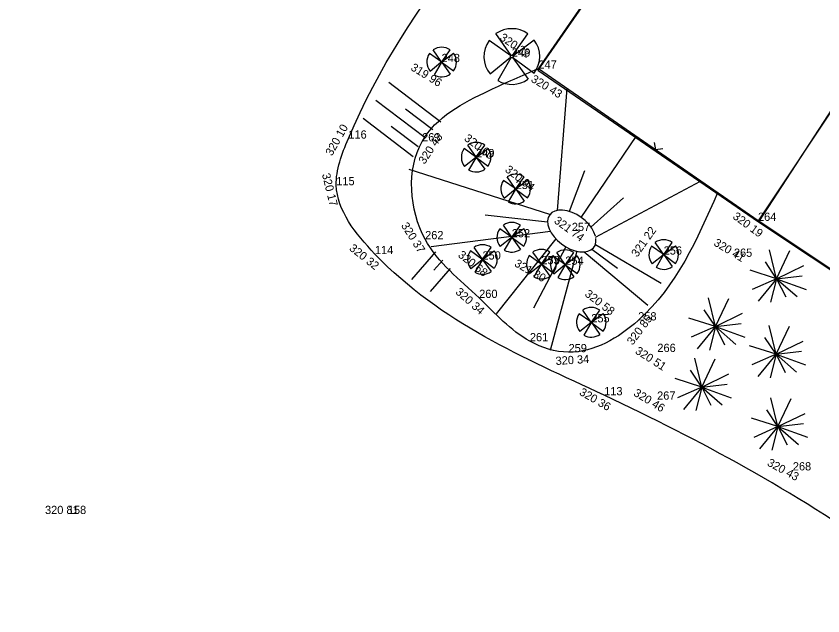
# Model space of a CAD drawing. Extents: x -742884 to -742543, y -1054677 to -1054433.
# Drawn here: x -742706.11 to -742676.68, y -1054570.07 to -1054548.2 of the extents above; entities that cross this region are included whole.
import ezdxf

# ---------------------------------------------------------------- set-up
doc = ezdxf.new("R2010")
doc.units = 0
for name, color, linetype in [('Vrstva 1', 7, 'Continuous'), ('Vrstva 10', 7, 'Continuous'), ('Vrstva 11', 7, 'Continuous'), ('Vrstva 2', 7, 'Continuous'), ('Vrstva 3', 7, 'Continuous'), ('Vrstva 5', 7, 'Continuous'), ('Vrstva 50', 7, 'Continuous'), ('Vrstva 6', 7, 'Continuous')]:
    doc.layers.add(name, color=color, linetype=linetype)

# ---------------------------------------------------------------- blocks, each defined once
blk = doc.blocks.new('Z15')
at = {"layer": 'Vrstva 2'}
for p, q in [((-10, 2), (-8, 6)), ((-10, -2), (-10, 2)), ((-8, 6), (-6, 8)), ((-6, 8), (-2, 10)), ((-2, 10), (2, 10)), ((2, 10), (6, 8)), ((6, 8), (8, 6)), ((8, 6), (10, 2)), ((10, 2), (10, -2)), ((-8, -6), (-10, -2)), ((-6, -8), (-8, -6)), ((-2, -10), (-6, -8)), ((2, -10), (-2, -10)), ((6, -8), (2, -10)), ((8, -6), (6, -8)), ((10, -2), (8, -6))]:
    blk.add_line(p, q, dxfattribs=at)

msp = doc.modelspace()

# ---------------------------------------------------------------- linework, layer by layer
at = {"layer": 'Vrstva 1'}
for p, q in [((-742690.59, -1054549.88), (-742690.59, -1054549.88)), ((-742688.03, -1054549.68), (-742688.03, -1054549.68)), ((-742687.06, -1054550.12), (-742687.06, -1054550.12)), ((-742693.99, -1054552.67), (-742693.99, -1054552.67)), ((-742691.3, -1054552.77), (-742691.3, -1054552.77)), ((-742689.33, -1054553.35), (-742689.33, -1054553.35)), ((-742694.43, -1054554.37), (-742694.43, -1054554.37)), ((-742687.89, -1054554.51), (-742687.89, -1054554.51)), ((-742679.05, -1054555.67), (-742679.05, -1054555.67)), ((-742685.84, -1054556.04), (-742685.84, -1054556.04)), ((-742691.19, -1054556.34), (-742691.19, -1054556.34)), ((-742688.03, -1054556.27), (-742688.03, -1054556.27)), ((-742693.02, -1054556.88), (-742693.02, -1054556.88)), ((-742682.49, -1054556.9), (-742682.49, -1054556.9)), ((-742679.93, -1054556.98), (-742679.93, -1054556.98)), ((-742689.1, -1054557.08), (-742689.1, -1054557.08)), ((-742686.95, -1054557.25), (-742686.95, -1054557.25)), ((-742686.08, -1054557.27), (-742686.08, -1054557.27)), ((-742689.22, -1054558.48), (-742689.22, -1054558.48)), ((-742685.13, -1054559.37), (-742685.13, -1054559.37)), ((-742683.42, -1054559.3), (-742683.42, -1054559.3)), ((-742687.37, -1054560.06), (-742687.37, -1054560.06)), ((-742685.96, -1054560.46), (-742685.96, -1054560.46)), ((-742682.72, -1054560.45), (-742682.72, -1054560.45)), ((-742684.66, -1054562.03), (-742684.66, -1054562.03)), ((-742682.73, -1054562.19), (-742682.73, -1054562.19)), ((-742677.78, -1054564.77), (-742677.78, -1054564.77)), ((-742704.22, -1054566.36), (-742704.22, -1054566.36))]:
    msp.add_line(p, q, dxfattribs=at)
at = {"layer": 'Vrstva 10'}
for p, q in [((-742688.054, -1054549.64), (-742688.608, -1054548.843)), ((-742688, -1054549.64), (-742687.439, -1054548.849)), ((-742687.992, -1054549.651), (-742687.212, -1054549.074)), ((-742688.07, -1054549.646), (-742688.858, -1054549.09)), ((-742690.611, -1054549.861), (-742691.031, -1054549.566)), ((-742690.602, -1054549.858), (-742690.897, -1054549.435)), ((-742690.574, -1054549.858), (-742690.276, -1054549.438)), ((-742690.57, -1054549.864), (-742690.156, -1054549.558)), ((-742690.611, -1054549.898), (-742691.01, -1054550.218)), ((-742690.605, -1054549.904), (-742690.862, -1054550.345)), ((-742690.573, -1054549.901), (-742690.276, -1054550.319)), ((-742690.566, -1054549.896), (-742690.156, -1054550.199)), ((-742688.071, -1054549.715), (-742688.82, -1054550.317)), ((-742688.06, -1054549.725), (-742688.541, -1054550.556)), ((-742687.996, -1054549.72), (-742687.438, -1054550.507)), ((-742687.986, -1054549.709), (-742687.212, -1054550.282)), ((-742689.342, -1054553.328), (-742689.637, -1054552.905)), ((-742689.314, -1054553.328), (-742689.016, -1054552.908)), ((-742689.351, -1054553.331), (-742689.771, -1054553.036)), ((-742689.31, -1054553.334), (-742688.896, -1054553.028)), ((-742689.351, -1054553.368), (-742689.75, -1054553.688)), ((-742689.345, -1054553.374), (-742689.602, -1054553.815)), ((-742689.313, -1054553.371), (-742689.016, -1054553.789)), ((-742689.306, -1054553.366), (-742688.896, -1054553.669)), ((-742687.902, -1054554.488), (-742688.197, -1054554.065)), ((-742687.874, -1054554.488), (-742687.576, -1054554.068)), ((-742687.911, -1054554.491), (-742688.331, -1054554.196)), ((-742687.87, -1054554.494), (-742687.456, -1054554.188)), ((-742687.911, -1054554.528), (-742688.31, -1054554.848)), ((-742687.905, -1054554.534), (-742688.162, -1054554.975)), ((-742687.873, -1054554.531), (-742687.576, -1054554.949)), ((-742687.866, -1054554.526), (-742687.456, -1054554.829)), ((-742688.042, -1054556.248), (-742688.337, -1054555.825)), ((-742688.014, -1054556.248), (-742687.716, -1054555.828)), ((-742688.051, -1054556.251), (-742688.471, -1054555.956)), ((-742688.01, -1054556.254), (-742687.596, -1054555.948)), ((-742688.051, -1054556.288), (-742688.45, -1054556.608)), ((-742688.045, -1054556.294), (-742688.302, -1054556.735)), ((-742688.013, -1054556.291), (-742687.716, -1054556.709)), ((-742688.006, -1054556.286), (-742687.596, -1054556.589)), ((-742689.112, -1054557.058), (-742689.407, -1054556.635)), ((-742689.084, -1054557.058), (-742688.786, -1054556.638)), ((-742682.511, -1054556.881), (-742682.931, -1054556.586)), ((-742682.502, -1054556.878), (-742682.797, -1054556.455)), ((-742682.474, -1054556.878), (-742682.176, -1054556.458)), ((-742682.47, -1054556.884), (-742682.056, -1054556.578)), ((-742678.372, -1054557.78), (-742678.629, -1054556.73)), ((-742689.121, -1054557.061), (-742689.541, -1054556.766)), ((-742689.08, -1054557.064), (-742688.666, -1054556.758)), ((-742686.971, -1054557.231), (-742687.391, -1054556.936)), ((-742686.962, -1054557.228), (-742687.257, -1054556.805)), ((-742686.934, -1054557.228), (-742686.636, -1054556.808)), ((-742686.93, -1054557.234), (-742686.516, -1054556.928)), ((-742686.101, -1054557.251), (-742686.521, -1054556.956)), ((-742686.092, -1054557.248), (-742686.387, -1054556.825)), ((-742686.064, -1054557.248), (-742685.766, -1054556.828)), ((-742686.06, -1054557.254), (-742685.646, -1054556.948)), ((-742682.511, -1054556.918), (-742682.91, -1054557.238)), ((-742682.505, -1054556.924), (-742682.762, -1054557.365)), ((-742682.473, -1054556.921), (-742682.176, -1054557.339)), ((-742682.466, -1054556.916), (-742682.056, -1054557.219)), ((-742678.372, -1054557.78), (-742677.887, -1054556.755)), ((-742689.121, -1054557.098), (-742689.52, -1054557.418)), ((-742689.115, -1054557.104), (-742689.372, -1054557.545)), ((-742689.083, -1054557.101), (-742688.786, -1054557.519)), ((-742689.076, -1054557.096), (-742688.666, -1054557.399)), ((-742686.971, -1054557.268), (-742687.37, -1054557.588)), ((-742686.965, -1054557.274), (-742687.222, -1054557.715)), ((-742686.933, -1054557.271), (-742686.636, -1054557.689)), ((-742686.926, -1054557.266), (-742686.516, -1054557.569)), ((-742686.101, -1054557.288), (-742686.5, -1054557.608)), ((-742686.095, -1054557.294), (-742686.352, -1054557.735)), ((-742686.063, -1054557.291), (-742685.766, -1054557.709)), ((-742686.056, -1054557.286), (-742685.646, -1054557.589)), ((-742678.372, -1054557.78), (-742678.782, -1054557.169)), ((-742678.372, -1054557.78), (-742677.38, -1054557.301)), ((-742678.372, -1054557.78), (-742679.341, -1054557.473)), ((-742678.372, -1054557.78), (-742679.257, -1054558.173)), ((-742678.372, -1054557.78), (-742679.042, -1054558.594)), ((-742678.372, -1054557.78), (-742678.592, -1054558.639)), ((-742678.376, -1054557.774), (-742678.376, -1054557.774)), ((-742678.372, -1054557.78), (-742677.44, -1054557.674)), ((-742678.372, -1054557.78), (-742678.372, -1054557.78)), ((-742678.372, -1054557.78), (-742678.036, -1054558.444)), ((-742678.372, -1054557.78), (-742677.297, -1054558.169)), ((-742678.372, -1054557.78), (-742677.626, -1054558.433)), ((-742678.372, -1054557.78), (-742678.372, -1054557.78)), ((-742680.602, -1054559.52), (-742680.859, -1054558.47)), ((-742680.602, -1054559.52), (-742680.117, -1054558.495)), ((-742685.151, -1054559.351), (-742685.571, -1054559.056)), ((-742685.142, -1054559.348), (-742685.437, -1054558.925)), ((-742685.114, -1054559.348), (-742684.816, -1054558.928)), ((-742685.11, -1054559.354), (-742684.696, -1054559.048)), ((-742680.602, -1054559.52), (-742681.012, -1054558.909)), ((-742680.602, -1054559.52), (-742679.61, -1054559.041)), ((-742680.602, -1054559.52), (-742681.571, -1054559.213)), ((-742685.151, -1054559.388), (-742685.55, -1054559.708)), ((-742685.145, -1054559.394), (-742685.402, -1054559.835)), ((-742685.113, -1054559.391), (-742684.816, -1054559.809)), ((-742685.106, -1054559.386), (-742684.696, -1054559.689)), ((-742680.602, -1054559.52), (-742681.487, -1054559.913)), ((-742680.602, -1054559.52), (-742681.272, -1054560.334)), ((-742680.602, -1054559.52), (-742680.822, -1054560.379)), ((-742680.606, -1054559.514), (-742680.606, -1054559.514)), ((-742680.602, -1054559.52), (-742679.67, -1054559.414)), ((-742680.602, -1054559.52), (-742680.602, -1054559.52)), ((-742680.602, -1054559.52), (-742680.266, -1054560.184)), ((-742680.602, -1054559.52), (-742679.527, -1054559.909)), ((-742680.602, -1054559.52), (-742679.856, -1054560.173)), ((-742680.602, -1054559.52), (-742680.602, -1054559.52)), ((-742678.392, -1054560.53), (-742678.649, -1054559.48)), ((-742678.392, -1054560.53), (-742677.907, -1054559.505)), ((-742678.392, -1054560.53), (-742678.802, -1054559.919)), ((-742678.392, -1054560.53), (-742679.361, -1054560.223)), ((-742678.392, -1054560.53), (-742677.4, -1054560.051)), ((-742678.392, -1054560.53), (-742679.277, -1054560.923)), ((-742678.392, -1054560.53), (-742679.062, -1054561.344)), ((-742678.392, -1054560.53), (-742678.612, -1054561.389)), ((-742678.396, -1054560.524), (-742678.396, -1054560.524)), ((-742678.392, -1054560.53), (-742677.46, -1054560.424)), ((-742678.392, -1054560.53), (-742678.392, -1054560.53)), ((-742678.392, -1054560.53), (-742678.056, -1054561.194)), ((-742678.392, -1054560.53), (-742677.317, -1054560.919)), ((-742678.392, -1054560.53), (-742677.646, -1054561.183)), ((-742678.392, -1054560.53), (-742678.392, -1054560.53)), ((-742681.102, -1054561.73), (-742681.359, -1054560.68)), ((-742681.102, -1054561.73), (-742680.617, -1054560.705)), ((-742681.102, -1054561.73), (-742681.512, -1054561.119)), ((-742681.102, -1054561.73), (-742682.071, -1054561.423)), ((-742681.102, -1054561.73), (-742680.11, -1054561.251)), ((-742681.102, -1054561.73), (-742681.987, -1054562.123)), ((-742681.102, -1054561.73), (-742681.772, -1054562.544)), ((-742681.102, -1054561.73), (-742681.322, -1054562.589)), ((-742681.106, -1054561.724), (-742681.106, -1054561.724)), ((-742681.102, -1054561.73), (-742680.17, -1054561.624)), ((-742681.102, -1054561.73), (-742681.102, -1054561.73)), ((-742681.102, -1054561.73), (-742680.766, -1054562.394)), ((-742681.102, -1054561.73), (-742680.027, -1054562.119)), ((-742681.102, -1054561.73), (-742680.356, -1054562.383)), ((-742681.102, -1054561.73), (-742681.102, -1054561.73)), ((-742678.322, -1054563.17), (-742678.579, -1054562.12)), ((-742678.322, -1054563.17), (-742677.837, -1054562.145)), ((-742678.322, -1054563.17), (-742678.732, -1054562.559)), ((-742678.322, -1054563.17), (-742679.291, -1054562.863)), ((-742678.322, -1054563.17), (-742677.33, -1054562.691)), ((-742678.322, -1054563.17), (-742679.207, -1054563.563)), ((-742678.322, -1054563.17), (-742678.992, -1054563.984)), ((-742678.322, -1054563.17), (-742678.542, -1054564.029)), ((-742678.326, -1054563.164), (-742678.326, -1054563.164)), ((-742678.322, -1054563.17), (-742677.39, -1054563.064)), ((-742678.322, -1054563.17), (-742678.322, -1054563.17)), ((-742678.322, -1054563.17), (-742677.986, -1054563.834)), ((-742678.322, -1054563.17), (-742677.247, -1054563.559)), ((-742678.322, -1054563.17), (-742677.576, -1054563.823)), ((-742678.322, -1054563.17), (-742678.322, -1054563.17))]:
    msp.add_line(p, q, dxfattribs=at)
for centre, radius, start, end in [((-742688.028, -1054549.677), 1.016, 54.7465, 124.8105), ((-742688.028, -1054549.677), 1.016, 323.4756, 36.2971), ((-742690.589, -1054549.878), 0.54, 54.7465, 124.8105), ((-742688.029, -1054549.675), 1.016, 144.8767, 218.9336), ((-742690.589, -1054549.877), 0.54, 144.8767, 218.9336), ((-742690.589, -1054549.878), 0.54, 323.4756, 36.2971), ((-742690.589, -1054549.878), 0.54, 239.6151, 305.4552), ((-742688.028, -1054549.677), 1.016, 239.6151, 305.4552), ((-742689.329, -1054553.348), 0.54, 54.7465, 124.8105), ((-742689.329, -1054553.347), 0.54, 144.8767, 218.9336), ((-742689.329, -1054553.348), 0.54, 323.4756, 36.2971), ((-742689.329, -1054553.348), 0.54, 239.6151, 305.4552), ((-742687.889, -1054554.508), 0.54, 54.7465, 124.8105), ((-742687.889, -1054554.507), 0.54, 144.8767, 218.9336), ((-742687.889, -1054554.508), 0.54, 323.4756, 36.2971), ((-742687.889, -1054554.508), 0.54, 239.6151, 305.4552), ((-742688.029, -1054556.268), 0.54, 54.7465, 124.8105), ((-742688.029, -1054556.267), 0.54, 144.8767, 218.9336), ((-742688.029, -1054556.268), 0.54, 323.4756, 36.2971), ((-742682.489, -1054556.898), 0.54, 54.7465, 124.8105), ((-742689.099, -1054557.078), 0.54, 54.7465, 124.8105), ((-742688.029, -1054556.268), 0.54, 239.6151, 305.4552), ((-742686.949, -1054557.248), 0.54, 54.7465, 124.8105), ((-742686.079, -1054557.268), 0.54, 54.7465, 124.8105), ((-742682.489, -1054556.897), 0.54, 144.8767, 218.9336), ((-742682.489, -1054556.898), 0.54, 323.4756, 36.2971), ((-742689.099, -1054557.077), 0.54, 144.8767, 218.9336), ((-742689.099, -1054557.078), 0.54, 323.4756, 36.2971), ((-742686.949, -1054557.247), 0.54, 144.8767, 218.9336), ((-742686.079, -1054557.267), 0.54, 144.8767, 218.9336), ((-742686.949, -1054557.248), 0.54, 323.4756, 36.2971), ((-742686.079, -1054557.268), 0.54, 323.4756, 36.2971), ((-742689.099, -1054557.078), 0.54, 239.6151, 305.4552), ((-742682.489, -1054556.898), 0.54, 239.6151, 305.4552), ((-742686.949, -1054557.248), 0.54, 239.6151, 305.4552), ((-742686.079, -1054557.268), 0.54, 239.6151, 305.4552), ((-742685.129, -1054559.367), 0.54, 144.8767, 218.9336), ((-742685.129, -1054559.368), 0.54, 54.7465, 124.8105), ((-742685.129, -1054559.368), 0.54, 323.4756, 36.2971), ((-742685.129, -1054559.368), 0.54, 239.6151, 305.4552)]:
    msp.add_arc(centre, radius, start, end, dxfattribs=at)
at = {"layer": 'Vrstva 11'}
for p, q in [((-742690.617, -1054552.07), (-742692.51, -1054550.628)), ((-742686.021, -1054550.84), (-742686.369, -1054555.288)), ((-742691.19, -1054552.644), (-742692.986, -1054551.284)), ((-742690.913, -1054552.352), (-742691.911, -1054551.592)), ((-742693.454, -1054551.93), (-742691.631, -1054553.318)), ((-742692.423, -1054552.219), (-742691.444, -1054552.961)), ((-742685.505, -1054555.542), (-742683.493, -1054552.592)), ((-742686.636, -1054555.436), (-742691.772, -1054553.8)), ((-742685.38, -1054553.85), (-742685.939, -1054555.325)), ((-742684.971, -1054556.265), (-742681.142, -1054554.22)), ((-742685.144, -1054555.896), (-742683.95, -1054554.83)), ((-742686.721, -1054555.719), (-742689.004, -1054555.461)), ((-742686.618, -1054556.054), (-742690.971, -1054556.612)), ((-742686.421, -1054556.324), (-742688.599, -1054559.064)), ((-742686.058, -1054556.614), (-742687.24, -1054558.85)), ((-742685.107, -1054556.706), (-742684.17, -1054557.39)), ((-742684.981, -1054556.53), (-742682.577, -1054557.944)), ((-742690.815, -1054556.799), (-742691.691, -1054557.802)), ((-742685.657, -1054556.777), (-742686.626, -1054560.393)), ((-742685.385, -1054556.801), (-742683.071, -1054558.739)), ((-742690.549, -1054557.108), (-742690.867, -1054557.472)), ((-742690.278, -1054557.409), (-742691.01, -1054558.251))]:
    msp.add_line(p, q, dxfattribs=at)
msp.add_ellipse((-742685.84, -1054556.04), major_axis=(0.808, -0.59), ratio=0.6, start_param=0.628585, end_param=6.806795, dxfattribs=at)
for points in [[(-742641.45, -1054542), (-742646.08, -1054542.32), (-742650.28, -1054545.1), (-742653.63, -1054549.14), (-742658.66, -1054557.13), (-742664.13, -1054565.84), (-742667.81, -1054569.62), (-742669.76, -1054570.07), (-742674.4, -1054567.88), (-742684.66, -1054562.03), (-742693.02, -1054556.88), (-742694.43, -1054554.37), (-742693.99, -1054552.67), (-742684.52, -1054539.64), (-742677.51, -1054529.95), (-742676.26, -1054526.54), (-742677.27, -1054522.39), (-742681.19, -1054517.29), (-742689.28, -1054510.73), (-742697.86, -1054505.14), (-742704.02, -1054502.75), (-742713.11, -1054501.07), (-742723.98, -1054503.51), (-742736.77, -1054510.1), (-742745.39, -1054515.75), (-742752.81, -1054521.82), (-742762.72, -1054531.38), (-742770.54, -1054539.36), (-742775.54, -1054544.64)], [(-742680.528, -1054554.646), (-742683.42, -1054559.3), (-742685.96, -1054560.46), (-742687.37, -1054560.06), (-742689.22, -1054558.48), (-742691.19, -1054556.34), (-742691.3, -1054552.77), (-742688.85, -1054550.91), (-742687.06, -1054550.12)]]:
    msp.add_spline(points, degree=3, dxfattribs=at)
at = {"layer": 'Vrstva 5'}
for p, q in [((-742679.05, -1054555.67), (-742687.06, -1054550.12)), ((-742682.837, -1054552.808), (-742682.789, -1054553.079)), ((-742682.518, -1054553.037), (-742682.789, -1054553.079))]:
    msp.add_line(p, q, dxfattribs=at)
msp.add_lwpolyline([(-742687.06, -1054550.12), (-742678.97, -1054538.42), (-742670.43, -1054526.08)], dxfattribs=at)
at = {"layer": 'Vrstva 50'}
msp.add_line((-742675.38, -1054550.09), (-742679.03, -1054555.7), dxfattribs=at)
msp.add_lwpolyline([(-742670.45, -1054526.06), (-742684.78, -1054546.85), (-742687.08, -1054550.18), (-742679.03, -1054555.7), (-742669.36, -1054562.14), (-742666.55, -1054557.95), (-742665.76, -1054556.77), (-742666.29, -1054556.4), (-742653.11, -1054537.36), (-742666.64, -1054528.55)], dxfattribs=at)
at = {"layer": 'Vrstva 6'}
for p in [(-742675.37, -1054550.134), (-742669.36, -1054562.11)]:
    msp.add_line(p, (-742679.05, -1054555.67), dxfattribs=at)

# ---------------------------------------------------------------- block references
at = {"layer": 'Vrstva 10'}
for p, xscale, yscale, rotation in [((-742688.03, -1054549.68), 0.005079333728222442, 0.005079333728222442, -30.671756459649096), ((-742690.59, -1054549.88), 0.0026993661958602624, 0.002699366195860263, -30.671756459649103), ((-742689.33, -1054553.35), 0.0026993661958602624, 0.002699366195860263, -30.671756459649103), ((-742687.89, -1054554.51), 0.0026993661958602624, 0.002699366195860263, -30.671756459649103), ((-742688.03, -1054556.27), 0.0026993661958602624, 0.002699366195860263, -30.671756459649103), ((-742682.49, -1054556.9), 0.0026993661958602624, 0.002699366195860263, -30.671756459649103), ((-742689.1, -1054557.08), 0.0026993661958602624, 0.002699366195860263, -30.671756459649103), ((-742686.95, -1054557.25), 0.0026993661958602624, 0.002699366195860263, -30.671756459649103), ((-742686.08, -1054557.27), 0.0026993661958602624, 0.002699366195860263, -30.671756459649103), ((-742685.13, -1054559.37), 0.0026993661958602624, 0.002699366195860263, -30.671756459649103)]:
    msp.add_blockref('Z15', p, dxfattribs=dict(at, xscale=xscale, yscale=yscale, rotation=rotation))

# ---------------------------------------------------------------- texts
at = {"layer": 'Vrstva 2'}
for s, p in [('246', (-742688.03, -1054549.68)), ('248', (-742690.59, -1054549.88)), ('247', (-742687.06, -1054550.12)), ('116', (-742693.99, -1054552.67)), ('263', (-742691.3, -1054552.77)), ('249', (-742689.33, -1054553.35)), ('115', (-742694.43, -1054554.37)), ('251', (-742687.89, -1054554.51)), ('264', (-742679.05, -1054555.67)), ('257', (-742685.84, -1054556.04)), ('262', (-742691.19, -1054556.34)), ('252', (-742688.03, -1054556.27)), ('114', (-742693.02, -1054556.88)), ('256', (-742682.49, -1054556.9)), ('265', (-742679.93, -1054556.98)), ('250', (-742689.1, -1054557.08)), ('253', (-742686.95, -1054557.25)), ('254', (-742686.08, -1054557.27)), ('260', (-742689.22, -1054558.48)), ('255', (-742685.13, -1054559.37)), ('258', (-742683.42, -1054559.3)), ('261', (-742687.37, -1054560.06)), ('259', (-742685.96, -1054560.46)), ('266', (-742682.72, -1054560.45)), ('113', (-742684.66, -1054562.03)), ('267', (-742682.73, -1054562.19)), ('268', (-742677.78, -1054564.77)), ('158', (-742704.22, -1054566.36))]:
    msp.add_text(s, height=0.3, dxfattribs=at).set_placement(p)
at = {"layer": 'Vrstva 3'}
for s, rotation, p in [('320 32 ', 325.7354, (-742688.495, -1054549.051)), ('319 96 ', 328.3313, (-742691.743, -1054550.152)), ('320 43 ', 328.8462, (-742687.356, -1054550.576)), ('320 10 ', 60.6422, (-742694.587, -1054553.322)), ('320 48 ', 56.6814, (-742691.209, -1054553.625)), ('320 60 ', 322.9484, (-742689.791, -1054552.712)), ('320 94 ', 321.7098, (-742688.302, -1054553.848)), ('320 17 ', 283.9664, (-742694.955, -1054553.972)), ('321 74 ', 323.7234, (-742686.515, -1054555.719)), ('320 19 ', 323.678, (-742679.998, -1054555.563)), ('320 37 ', 302.4643, (-742692.079, -1054555.841)), ('321 22 ', 54.5301, (-742683.453, -1054557.014)), ('320 41 ', 328.8972, (-742680.693, -1054556.547)), ('320 32 ', 321.7291, (-742693.982, -1054556.716)), ('320 68 ', 321.3816, (-742690.016, -1054556.958)), ('321 30 ', 329.9876, (-742687.96, -1054557.304)), ('320 34 ', 318.5424, (-742690.106, -1054558.3)), ('320 58 ', 322.5641, (-742685.393, -1054558.387)), ('320 85 ', 53.2525, (-742683.621, -1054560.223)), ('320 34 ', 3.5165, (-742686.423, -1054560.926)), ('320 51 ', 327.2236, (-742683.554, -1054560.483)), ('320 36 ', 329.9001, (-742685.593, -1054561.996)), ('320 46 ', 328.7133, (-742683.614, -1054562.022)), ('320 43 ', 331.4769, (-742678.739, -1054564.577))]:
    msp.add_text(s, height=0.3, rotation=rotation, dxfattribs=at).set_placement(p)
msp.add_text('320 81 ', height=0.3, dxfattribs=at).set_placement((-742705.053, -1054566.36))

doc.saveas('drawing.dxf')
